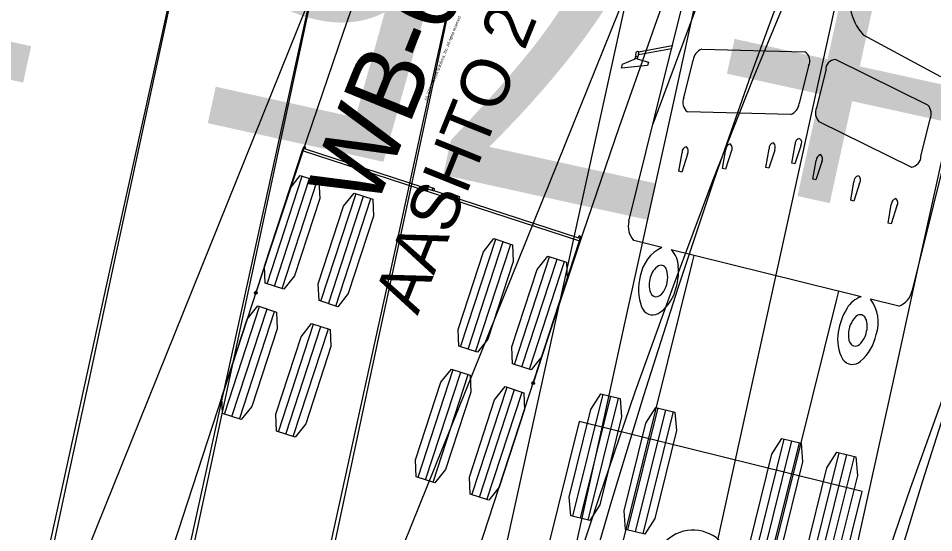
# Model space of a CAD drawing. Extents: x -69 to 14108008, y -6 to 8640172.
# Drawn here: x 14107714.03 to 14107740.71, y 8639789.08 to 8639804.08 of the extents above; entities that cross this region are included whole.
import ezdxf

# ---------------------------------------------------------------- set-up
doc = ezdxf.new("R2010")
doc.units = 0
for name, color, linetype in [('Alignment', 7, 'Continuous'), ('AutoTurn2', 7, 'Continuous'), ('AutoTurn3', 7, 'Continuous'), ('AutoTurn4', 7, 'Continuous'), ('AutoTurn5', 7, 'Continuous'), ('TextAlignment', 7, 'Continuous')]:
    doc.layers.add(name, color=color, linetype=linetype)

msp = doc.modelspace()

# ---------------------------------------------------------------- linework, layer by layer
at = {"layer": 'Alignment'}
msp.add_line((14107732.613, 8639808.607), (14107547.946, 8638968.472), dxfattribs=at)
at = {"layer": 'AutoTurn2'}
for p, q in [((14107732.528, 8639801.003), (14107736.093, 8639810.561)), ((14107738.651, 8639803.594), (14107740.905, 8639802.38)), ((14107733.069, 8639803.187), (14107733.094, 8639803.284)), ((14107733.95, 8639803.177), (14107736.955, 8639803.096)), ((14107732.034, 8639802.905), (14107732.008, 8639802.894)), ((14107732.061, 8639802.897), (14107732.034, 8639802.905)), ((14107733.428, 8639801.76), (14107733.7, 8639802.857)), ((14107740.537, 8639801.544), (14107737.842, 8639802.876)), ((14107737.058, 8639802.689), (14107736.786, 8639801.592)), ((14107737.561, 8639802.564), (14107737.289, 8639801.467)), ((14107736.536, 8639801.272), (14107733.531, 8639801.353)), ((14107737.36, 8639801.068), (14107740.055, 8639799.735)), ((14107740.336, 8639800.047), (14107740.608, 8639801.145)), ((14107733.28, 8639799.616), (14107733.374, 8639800.159)), ((14107734.554, 8639799.697), (14107734.654, 8639800.265)), ((14107734.817, 8639800.224), (14107734.642, 8639799.675)), ((14107735.816, 8639799.729), (14107735.911, 8639800.271)), ((14107736.074, 8639800.231), (14107735.904, 8639799.707)), ((14107736.576, 8639799.858), (14107736.671, 8639800.401)), ((14107736.834, 8639800.36), (14107736.664, 8639799.836)), ((14107733.537, 8639800.118), (14107733.367, 8639799.594)), ((14107737.188, 8639799.388), (14107737.282, 8639799.931)), ((14107737.445, 8639799.891), (14107737.275, 8639799.367)), ((14107733.367, 8639799.594), (14107733.28, 8639799.616)), ((14107734.642, 8639799.675), (14107734.554, 8639799.697)), ((14107735.904, 8639799.707), (14107735.816, 8639799.729)), ((14107736.664, 8639799.836), (14107736.576, 8639799.858)), ((14107737.275, 8639799.367), (14107737.188, 8639799.388)), ((14107738.289, 8639798.771), (14107738.383, 8639799.314)), ((14107738.547, 8639799.273), (14107738.376, 8639798.749)), ((14107738.376, 8639798.749), (14107738.289, 8639798.771)), ((14107739.378, 8639798.104), (14107739.472, 8639798.647)), ((14107739.635, 8639798.606), (14107739.465, 8639798.082)), ((14107739.465, 8639798.082), (14107739.378, 8639798.104)), ((14107732.784, 8639797.397), (14107731.964, 8639797.6)), ((14107737.927, 8639796.121), (14107733.724, 8639797.164)), ((14107739.687, 8639795.685), (14107738.867, 8639795.888)), ((14107731.066, 8639793.118), (14107730.184, 8639789.559)), ((14107731.289, 8639793.062), (14107730.406, 8639789.504)), ((14107731.511, 8639793.007), (14107730.629, 8639789.448)), ((14107732.668, 8639792.72), (14107731.785, 8639789.162)), ((14107732.89, 8639792.665), (14107732.008, 8639789.106)), ((14107733.113, 8639792.61), (14107732.23, 8639789.051)), ((14107736.34, 8639791.81), (14107735.457, 8639788.251)), ((14107736.562, 8639791.755), (14107735.68, 8639788.196)), ((14107736.785, 8639791.7), (14107735.902, 8639788.141)), ((14107737.941, 8639791.413), (14107737.059, 8639787.854)), ((14107738.164, 8639791.358), (14107737.281, 8639787.799)), ((14107738.386, 8639791.302), (14107737.504, 8639787.744))]:
    msp.add_line(p, q, dxfattribs=at)
for points in [[(14107732.105, 8639803.098), (14107733.084, 8639803.282), (14107733.095, 8639803.292), (14107734.842, 8639810.335)], [(14107721.115, 8639754.96), (14107721.925, 8639758.191), (14107722.741, 8639761.419), (14107723.567, 8639764.642), (14107724.407, 8639767.858), (14107725.264, 8639771.068), (14107726.14, 8639774.268), (14107727.041, 8639777.458), (14107727.968, 8639780.636), (14107728.926, 8639783.799), (14107729.917, 8639786.947), (14107730.945, 8639790.078), (14107732.012, 8639793.189), (14107733.121, 8639796.279), (14107734.274, 8639799.346), (14107735.474, 8639802.388), (14107736.723, 8639805.403)], [(14107730.168, 8639756.118), (14107730.979, 8639759.324), (14107731.797, 8639762.516), (14107732.627, 8639765.693), (14107733.47, 8639768.853), (14107734.331, 8639771.996), (14107735.212, 8639775.118), (14107736.117, 8639778.219), (14107737.049, 8639781.297), (14107738.011, 8639784.351), (14107739.005, 8639787.38), (14107740.035, 8639790.381), (14107741.102, 8639793.354), (14107742.209, 8639796.297), (14107743.358, 8639799.21), (14107744.551, 8639802.09), (14107745.789, 8639804.936)], [(14107731.823, 8639798.163), (14107733.069, 8639803.187), (14107732.103, 8639803.009), (14107732.102, 8639803.009), (14107732.082, 8639802.977), (14107732.081, 8639802.976), (14107732.081, 8639802.975), (14107732.061, 8639802.898), (14107732.062, 8639802.897), (14107732.396, 8639802.797), (14107732.371, 8639802.698), (14107731.611, 8639802.621), (14107731.61, 8639802.622), (14107731.638, 8639802.737), (14107731.641, 8639802.739), (14107732.006, 8639802.893), (14107732.009, 8639802.895), (14107732.03, 8639802.979)], [(14107742.141, 8639800.472), (14107742.121, 8639800.388), (14107742.122, 8639800.385), (14107742.373, 8639800.077), (14107742.375, 8639800.075), (14107742.346, 8639799.96), (14107742.345, 8639799.96), (14107741.708, 8639800.382), (14107741.733, 8639800.482), (14107742.075, 8639800.414), (14107742.076, 8639800.414), (14107742.095, 8639800.492), (14107742.095, 8639800.493), (14107742.095, 8639800.494), (14107742.092, 8639800.532), (14107742.092, 8639800.532), (14107741.32, 8639801.141), (14107740.074, 8639796.117)], [(14107738.593, 8639795.956), (14107737.928, 8639796.121), (14107737.87, 8639795.89), (14107735.376, 8639785.833), (14107733.274, 8639786.354), (14107731.173, 8639786.875), (14107733.666, 8639796.932), (14107733.723, 8639797.164), (14107733.058, 8639797.329)], [(14107725.866, 8639738.913), (14107725.887, 8639738.908), (14107725.904, 8639738.976), (14107727.269, 8639744.477), (14107738.627, 8639790.281), (14107734.502, 8639791.304), (14107730.377, 8639792.327), (14107719.019, 8639746.523), (14107717.655, 8639741.022), (14107717.638, 8639740.953), (14107717.659, 8639740.948)]]:
    msp.add_lwpolyline(points, dxfattribs=at)
for points in [[(14107731.011, 8639793.131), (14107731.566, 8639792.994), (14107731.61, 8639792.454), (14107730.975, 8639789.891), (14107730.684, 8639789.435), (14107730.129, 8639789.572), (14107730.085, 8639790.112), (14107730.72, 8639792.674)], [(14107732.613, 8639792.734), (14107733.168, 8639792.596), (14107733.212, 8639792.057), (14107732.576, 8639789.494), (14107732.285, 8639789.038), (14107731.73, 8639789.175), (14107731.686, 8639789.715), (14107732.322, 8639792.277)], [(14107736.285, 8639791.824), (14107736.84, 8639791.686), (14107736.884, 8639791.146), (14107736.248, 8639788.584), (14107735.957, 8639788.127), (14107735.402, 8639788.265), (14107735.359, 8639788.804), (14107735.994, 8639791.367)], [(14107737.886, 8639791.426), (14107738.441, 8639791.289), (14107738.485, 8639790.749), (14107737.85, 8639788.187), (14107737.559, 8639787.73), (14107737.004, 8639787.868), (14107736.96, 8639788.407), (14107737.595, 8639790.97)]]:
    msp.add_lwpolyline(points, close=True, dxfattribs=at)
for centre, radius, start, end in [((14107739.777, 8639804.611), 1.517, 157.6535, 222.081), ((14107732.081, 8639803.052), 0.0522, 62.3363, 167.1909), ((14107734.085, 8639802.815), 0.387, 110.4063, 173.6383), ((14107736.804, 8639802.841), 0.296, 329.0571, 59.3547), ((14107732.129, 8639803.021), 0.108, 156.9147, 203.0972), ((14107737.856, 8639802.58), 0.296, 92.7923, 183.0899), ((14107733.729, 8639801.62), 0.332, 154.9949, 233.4169), ((14107736.401, 8639801.634), 0.387, 290.4088, 353.6359), ((14107740.248, 8639801.286), 0.387, 338.5087, 41.7406), ((14107737.648, 8639801.325), 0.387, 158.5111, 221.7382), ((14107734.804, 8639800.258), 0.157, 99.6195, 186.7291), ((14107734.648, 8639800.283), 0.184, 333.0267, 44.9187), ((14107736.067, 8639800.29), 0.157, 99.6195, 186.7291), ((14107735.91, 8639800.314), 0.184, 333.0267, 44.9187), ((14107736.826, 8639800.419), 0.157, 99.6195, 186.7291), ((14107736.705, 8639800.449), 0.157, 325.4179, 52.5275), ((14107733.53, 8639800.177), 0.157, 99.6195, 186.7291), ((14107733.373, 8639800.202), 0.184, 333.0267, 44.9187), ((14107737.466, 8639799.929), 0.184, 107.2283, 179.1203), ((14107737.316, 8639799.98), 0.157, 325.4179, 52.5275), ((14107740.004, 8639800.064), 0.332, 278.7301, 357.1521), ((14107738.567, 8639799.311), 0.184, 107.2283, 179.1203), ((14107738.417, 8639799.362), 0.157, 325.4179, 52.5275), ((14107739.656, 8639798.644), 0.184, 107.2283, 179.1203), ((14107739.506, 8639798.695), 0.157, 325.4179, 52.5275), ((14107732.424, 8639798.014), 0.619, 166.0715, 221.9132), ((14107733.277, 8639796.373), 1.136, 115.7034, 170.4947), ((14107732.537, 8639796.819), 0.729, 1.882, 44.396), ((14107732.96, 8639796.412), 0.522, 121.0789, 168.243), ((14107732.761, 8639796.706), 0.169, 14.5078, 114.6265), ((14107732.226, 8639796.528), 0.732, 331.2473, 17.4818), ((14107731.541, 8639796.701), 1.73, 339.9001, 4.6986), ((14107733.518, 8639796.17), 1.416, 164.0016, 201.0695), ((14107733.077, 8639796.301), 0.664, 160.9773, 199.199), ((14107732.529, 8639796.304), 0.362, 290.3701, 339.411), ((14107732.615, 8639796.131), 0.172, 196.3751, 283.5257), ((14107732.077, 8639796.432), 1.136, 301.8375, 343.3582), ((14107738.815, 8639795.262), 0.729, 107.751, 150.265), ((14107737.953, 8639795.213), 1.136, 341.6523, 36.4436), ((14107739.473, 8639796.266), 0.619, 290.2338, 346.0755), ((14107732.522, 8639795.776), 0.346, 199.4662, 296.4792), ((14107739.641, 8639794.692), 1.73, 147.4483, 172.2469), ((14107738.954, 8639794.86), 0.732, 134.6652, 180.8997), ((14107738.564, 8639795.267), 0.169, 37.5205, 137.6392), ((14107738.251, 8639795.1), 0.522, 343.904, 31.0681), ((14107739.041, 8639794.705), 1.136, 168.7888, 210.3095), ((14107738.582, 8639794.803), 0.362, 172.736, 221.7769), ((14107738.096, 8639795.057), 0.664, 312.948, 351.1697), ((14107737.645, 8639795.147), 1.416, 311.0775, 348.1453), ((14107738.425, 8639794.691), 0.172, 228.6213, 315.7719), ((14107738.341, 8639794.333), 0.346, 215.6677, 312.6808), ((14107733.691, 8639788.012), 1.143, 301.0735, 211.0735)]:
    msp.add_arc(centre, radius, start, end, dxfattribs=at)
for major_axis, start_param, end_param in [((-0.0188, -0.0759), 1.301202, 2.571945), ((0.0188, 0.0759), 2.615166, 3.884468)]:
    msp.add_ellipse((14107732.067, 8639803.039), major_axis=major_axis, ratio=0.544872, start_param=start_param, end_param=end_param, dxfattribs=at)
at = {"layer": 'AutoTurn3'}
msp.add_line((14107725.593, 8639748.722), (14107738.539, 8639807.621), dxfattribs=at)
for points in [[(14107723.117, 8639756.089), (14107723.832, 8639759.343), (14107724.547, 8639762.597), (14107725.262, 8639765.851), (14107725.978, 8639769.105), (14107726.693, 8639772.359), (14107727.408, 8639775.613), (14107728.123, 8639778.868), (14107728.839, 8639782.122), (14107729.554, 8639785.376), (14107730.269, 8639788.63), (14107730.985, 8639791.884), (14107731.7, 8639795.138), (14107732.415, 8639798.392), (14107733.13, 8639801.646), (14107733.846, 8639804.9), (14107734.561, 8639808.154), (14107735.319, 8639811.429), (14107736.171, 8639814.696), (14107737.115, 8639817.948), (14107738.151, 8639821.182), (14107739.278, 8639824.393), (14107740.494, 8639827.578), (14107741.8, 8639830.733)], [(14107730.93, 8639754.372), (14107731.645, 8639757.626), (14107732.361, 8639760.88), (14107733.076, 8639764.134), (14107733.791, 8639767.388), (14107734.506, 8639770.642), (14107735.222, 8639773.896), (14107735.937, 8639777.15), (14107736.652, 8639780.404), (14107737.368, 8639783.658), (14107738.083, 8639786.912), (14107738.798, 8639790.166), (14107739.513, 8639793.42), (14107740.229, 8639796.675), (14107740.944, 8639799.929), (14107741.659, 8639803.183), (14107742.374, 8639806.437)], [(14107722.512, 8639754.486), (14107723.233, 8639757.738), (14107723.961, 8639760.986), (14107724.698, 8639764.231), (14107725.447, 8639767.472), (14107726.212, 8639770.707), (14107726.995, 8639773.935), (14107727.8, 8639777.154), (14107728.63, 8639780.364), (14107729.488, 8639783.563), (14107730.377, 8639786.749), (14107731.3, 8639789.922), (14107732.26, 8639793.078), (14107733.259, 8639796.217), (14107734.3, 8639799.338), (14107735.385, 8639802.438), (14107736.516, 8639805.517)], [(14107731.53, 8639755.89), (14107732.253, 8639759.118), (14107732.984, 8639762.336), (14107733.725, 8639765.541), (14107734.479, 8639768.731), (14107735.249, 8639771.906), (14107736.039, 8639775.064), (14107736.851, 8639778.204), (14107737.688, 8639781.325), (14107738.553, 8639784.425), (14107739.449, 8639787.503), (14107740.378, 8639790.559), (14107741.343, 8639793.59), (14107742.346, 8639796.596), (14107743.389, 8639799.576), (14107744.473, 8639802.529), (14107745.601, 8639805.453)]]:
    msp.add_lwpolyline(points, dxfattribs=at)
at = {"layer": 'AutoTurn4'}
msp.add_line((14107725.743, 8639819.502), (14107713.52, 8639762.474), dxfattribs=at)
for points in [[(14107724.402, 8639830.154), (14107723.454, 8639826.846), (14107722.598, 8639823.512), (14107721.834, 8639820.161), (14107721.108, 8639816.83), (14107720.389, 8639813.51), (14107719.673, 8639810.199), (14107718.961, 8639806.896), (14107718.251, 8639803.599), (14107717.544, 8639800.309), (14107716.838, 8639797.023), (14107716.134, 8639793.742), (14107715.43, 8639790.464), (14107714.728, 8639787.189), (14107714.026, 8639783.916), (14107713.325, 8639780.646), (14107712.624, 8639777.378), (14107711.924, 8639774.111), (14107711.223, 8639770.845), (14107710.524, 8639767.58), (14107709.824, 8639764.316), (14107709.614, 8639763.337)], [(14107732.65, 8639830.011), (14107731.703, 8639826.931), (14107730.841, 8639823.826), (14107730.066, 8639820.699), (14107729.375, 8639817.546), (14107728.703, 8639814.357), (14107728.026, 8639811.159), (14107727.344, 8639807.951), (14107726.659, 8639804.736), (14107725.971, 8639801.514), (14107725.282, 8639798.287), (14107724.591, 8639795.055), (14107723.898, 8639791.819), (14107723.204, 8639788.579), (14107722.51, 8639785.336), (14107721.815, 8639782.091), (14107721.119, 8639778.844), (14107720.423, 8639775.595), (14107719.726, 8639772.344), (14107719.029, 8639769.093), (14107718.332, 8639765.84), (14107717.635, 8639762.586), (14107717.425, 8639761.61)], [(14107732.513, 8639829.395), (14107732.493, 8639829.403), (14107732.466, 8639829.337), (14107730.347, 8639824.081), (14107712.705, 8639780.311), (14107716.647, 8639778.723), (14107720.589, 8639777.134), (14107738.231, 8639820.904), (14107740.349, 8639826.16), (14107740.375, 8639826.226), (14107740.355, 8639826.234)]]:
    msp.add_lwpolyline(points, dxfattribs=at)
at = {"layer": 'AutoTurn5'}
for p, q in [((14107724.986, 8639815.832), (14107706.661, 8639732.465)), ((14107722.306, 8639800.221), (14107730.387, 8639797.586)), ((14107721.281, 8639796.339), (14107722.304, 8639799.476)), ((14107721.499, 8639796.268), (14107722.522, 8639799.405)), ((14107721.717, 8639796.197), (14107722.74, 8639799.334)), ((14107725.864, 8639799.135), (14107726.116, 8639799.053)), ((14107722.85, 8639795.827), (14107723.873, 8639798.965)), ((14107723.068, 8639795.756), (14107724.091, 8639798.893)), ((14107723.286, 8639795.685), (14107724.309, 8639798.822)), ((14107726.615, 8639798.89), (14107726.119, 8639799.052)), ((14107726.369, 8639798.97), (14107726.347, 8639798.903)), ((14107726.621, 8639798.888), (14107726.874, 8639798.806)), ((14107726.922, 8639794.499), (14107727.945, 8639797.637)), ((14107727.14, 8639794.428), (14107728.163, 8639797.565)), ((14107727.358, 8639794.357), (14107728.381, 8639797.494)), ((14107728.491, 8639793.988), (14107729.514, 8639797.125)), ((14107728.709, 8639793.917), (14107729.732, 8639797.054)), ((14107728.927, 8639793.845), (14107729.95, 8639796.983)), ((14107720.041, 8639792.536), (14107721.064, 8639795.673)), ((14107720.259, 8639792.465), (14107721.282, 8639795.602)), ((14107720.477, 8639792.394), (14107721.5, 8639795.531)), ((14107721.61, 8639792.024), (14107722.633, 8639795.162)), ((14107721.828, 8639791.953), (14107722.851, 8639795.091)), ((14107722.046, 8639791.882), (14107723.069, 8639795.02)), ((14107725.682, 8639790.696), (14107726.705, 8639793.834)), ((14107725.9, 8639790.625), (14107726.923, 8639793.763)), ((14107726.118, 8639790.554), (14107727.141, 8639793.692)), ((14107727.251, 8639790.185), (14107728.274, 8639793.322)), ((14107727.469, 8639790.114), (14107728.492, 8639793.251)), ((14107727.686, 8639790.043), (14107728.71, 8639793.18))]:
    msp.add_line(p, q, dxfattribs=at)
for points in [[(14107734.635, 8639831.615), (14107733.254, 8639828.586), (14107731.914, 8639825.533), (14107730.612, 8639822.46), (14107729.348, 8639819.369), (14107728.118, 8639816.261), (14107726.922, 8639813.138), (14107725.756, 8639810.002), (14107724.62, 8639806.854), (14107723.512, 8639803.695), (14107722.429, 8639800.527), (14107721.372, 8639797.35), (14107720.955, 8639796.077)], [(14107743.709, 8639830.917), (14107742.341, 8639828.029), (14107741.011, 8639825.11), (14107739.717, 8639822.163), (14107738.458, 8639819.19), (14107737.232, 8639816.193), (14107736.038, 8639813.173), (14107734.873, 8639810.134), (14107733.737, 8639807.076), (14107732.627, 8639804.002), (14107731.543, 8639800.912), (14107730.483, 8639797.808), (14107729.445, 8639794.692), (14107729.036, 8639793.442)], [(14107718.866, 8639806.556), (14107718.136, 8639803.255), (14107717.409, 8639799.961), (14107716.684, 8639796.673), (14107715.961, 8639793.39), (14107715.239, 8639790.111), (14107714.519, 8639786.835), (14107713.799, 8639783.562), (14107713.079, 8639780.292), (14107712.361, 8639777.024), (14107711.643, 8639773.758), (14107710.925, 8639770.493), (14107710.208, 8639767.229), (14107709.49, 8639763.967), (14107708.773, 8639760.706), (14107708.057, 8639757.445), (14107707.34, 8639754.185)], [(14107726.525, 8639804.27), (14107725.823, 8639801.056), (14107725.119, 8639797.837), (14107724.412, 8639794.612), (14107723.703, 8639791.382), (14107722.994, 8639788.147), (14107722.283, 8639784.91), (14107721.571, 8639781.669), (14107720.858, 8639778.427), (14107720.145, 8639775.181), (14107719.432, 8639771.935), (14107718.718, 8639768.686), (14107718.004, 8639765.437), (14107717.29, 8639762.186), (14107716.575, 8639758.934), (14107715.86, 8639755.682)], [(14107722.349, 8639800.281), (14107722.329, 8639800.288), (14107722.307, 8639800.221), (14107720.549, 8639794.833), (14107705.918, 8639749.967), (14107709.958, 8639748.649), (14107713.999, 8639747.332), (14107728.63, 8639792.198), (14107730.387, 8639797.586), (14107730.409, 8639797.653), (14107730.388, 8639797.66)], [(14107726.141, 8639799.119), (14107725.887, 8639799.202), (14107725.885, 8639799.202), (14107725.864, 8639799.135), (14107725.83, 8639799.146), (14107722.373, 8639800.273), (14107722.372, 8639800.274)], [(14107730.365, 8639797.667), (14107730.364, 8639797.668), (14107726.908, 8639798.795), (14107726.874, 8639798.806), (14107726.896, 8639798.872), (14107726.894, 8639798.873), (14107726.641, 8639798.956)]]:
    msp.add_lwpolyline(points, dxfattribs=at)
for points in [[(14107721.771, 8639796.179), (14107721.227, 8639796.356), (14107721.207, 8639796.849), (14107721.943, 8639799.108), (14107722.25, 8639799.494), (14107722.794, 8639799.316), (14107722.815, 8639798.824), (14107722.078, 8639796.565)], [(14107723.34, 8639795.667), (14107722.796, 8639795.845), (14107722.775, 8639796.337), (14107723.512, 8639798.596), (14107723.819, 8639798.982), (14107724.363, 8639798.805), (14107724.383, 8639798.312), (14107723.647, 8639796.053)], [(14107727.412, 8639794.339), (14107726.868, 8639794.517), (14107726.848, 8639795.009), (14107727.584, 8639797.268), (14107727.891, 8639797.654), (14107728.435, 8639797.477), (14107728.456, 8639796.984), (14107727.719, 8639794.725)], [(14107728.981, 8639793.828), (14107728.437, 8639794.005), (14107728.416, 8639794.498), (14107729.153, 8639796.757), (14107729.46, 8639797.143), (14107730.004, 8639796.965), (14107730.024, 8639796.473), (14107729.288, 8639794.214)], [(14107720.531, 8639792.376), (14107719.987, 8639792.553), (14107719.966, 8639793.046), (14107720.703, 8639795.305), (14107721.01, 8639795.691), (14107721.554, 8639795.513), (14107721.575, 8639795.021), (14107720.838, 8639792.762)], [(14107722.1, 8639791.865), (14107721.556, 8639792.042), (14107721.535, 8639792.535), (14107722.272, 8639794.793), (14107722.579, 8639795.179), (14107723.123, 8639795.002), (14107723.143, 8639794.509), (14107722.407, 8639792.25)], [(14107726.172, 8639790.537), (14107725.628, 8639790.714), (14107725.607, 8639791.207), (14107726.344, 8639793.465), (14107726.651, 8639793.851), (14107727.195, 8639793.674), (14107727.216, 8639793.181), (14107726.479, 8639790.922)], [(14107727.741, 8639790.025), (14107727.197, 8639790.202), (14107727.176, 8639790.695), (14107727.913, 8639792.954), (14107728.22, 8639793.34), (14107728.764, 8639793.162), (14107728.784, 8639792.67), (14107728.048, 8639790.411)]]:
    msp.add_lwpolyline(points, close=True, dxfattribs=at)
for centre, radius in [((14107722.371, 8639800.31), 0.0266), ((14107730.387, 8639797.696), 0.0266), ((14107720.955, 8639796.077), 0.0417), ((14107729.036, 8639793.442), 0.0417)]:
    msp.add_circle(centre, radius, dxfattribs=at)
for centre, radius, start, end in [((14107722.976, 8639802.203), 2.022, 251.9382, 252.622), ((14107726.129, 8639799.086), 0.0354, 76.2298, 248.4152), ((14107726.13, 8639799.086), 0.0352, 252.9125, 71.9129), ((14107726.63, 8639798.923), 0.0352, 71.9635, 250.9639), ((14107726.63, 8639798.922), 0.0353, 255.2744, 73.624), ((14107730.387, 8639797.696), 0.0363, 271.0157, 232.177)]:
    msp.add_arc(centre, radius, start, end, dxfattribs=at)

# ---------------------------------------------------------------- texts
at = {"layer": 'AutoTurn4'}
for s, height, p in [('AASHTO 2018 (US)', 1.41667, (14107725.666, 8639795.395)), ('WB-67', 2.125, (14107724.41, 8639798.437)), ('(c) 2023 Transoft Solutions, Inc. All rights reserved.', 0.085, (14107725.942, 8639801.671))]:
    msp.add_text(s, height=height, rotation=68.0477, dxfattribs=at).set_placement(p)
at = {"layer": 'TextAlignment'}
msp.add_text('10291+75.75', height=10.02, rotation=167.6032, dxfattribs=at).set_placement((14107779.22, 8639798.163))

doc.saveas('drawing.dxf')
